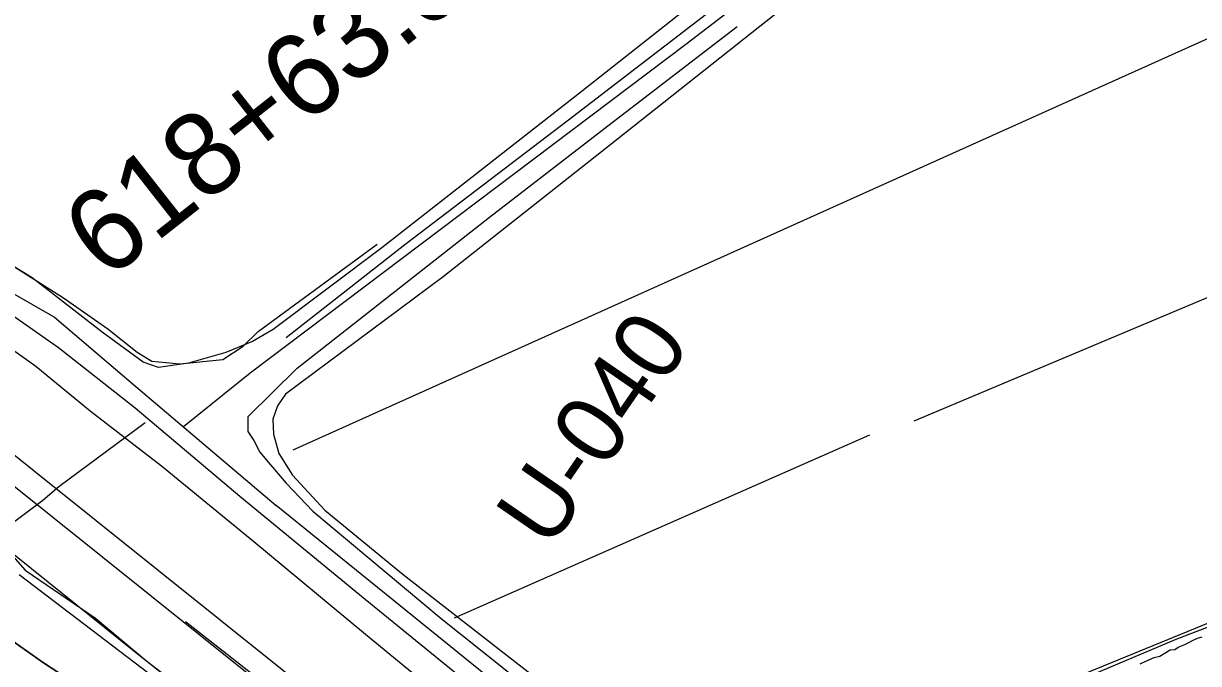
# Model space of a CAD drawing. Extents: x 3329297 to 3367176, y 649250 to 674653.
# Drawn here: x 3339953 to 3341368, y 669863 to 670634 of the extents above; entities that cross this region are included whole.
import ezdxf

# ---------------------------------------------------------------- set-up
doc = ezdxf.new("R2010")
doc.units = 0
for name, color, linetype in [('V-BORW-LINE', 7, 'Continuous'), ('V-DTCH-CNTR', 7, 'Continuous'), ('V-FLOD-BASE', 7, 'Continuous'), ('V-LEVE-TOET', 7, 'Continuous'), ('V-RIVR-RANG-IDEN', 7, 'Continuous'), ('V-ROAD-CNTR', 7, 'Continuous'), ('V-SITE-VEGE', 7, 'Continuous'), ('V-SURV-IDEN', 7, 'Continuous'), ('V-SURV-LINE', 7, 'Continuous'), ('V-TOPO-SHOR', 7, 'Continuous'), ('V-UTIL-LINE', 7, 'Continuous'), ('V-WETL-SWMP', 7, 'Continuous')]:
    doc.layers.add(name, color=color, linetype=linetype)

msp = doc.modelspace()

# ---------------------------------------------------------------- linework, layer by layer
at = {"layer": 'V-BORW-LINE'}
for points in [[(3338746.2, 670499.1), (3338751.5, 670497.1), (3339072.9, 670329.3), (3339297.5, 670198.9), (3339509.9, 670071.7), (3339743.3, 669952.6), (3339874.8, 669804.3), (3340076.4, 669714), (3340201.3, 669657), (3340187.6, 669710.9), (3340092.4, 669788.9), (3339977.3, 669864.2), (3339881.3, 669931.4), (3339745.1, 670037.3), (3339620.9, 670105.1), (3339504.8, 670191.3), (3339378.1, 670257.4), (3339267.1, 670330.2)], [(3339881.3, 669931.4), (3339977.3, 669864.2), (3340092.4, 669788.9), (3340187.6, 669710.9), (3340201.3, 669657), (3340076.4, 669714), (3339874.8, 669804.3)]]:
    msp.add_lwpolyline(points, dxfattribs=at)
at = {"layer": 'V-DTCH-CNTR'}
msp.add_lwpolyline([(3340905.5, 670682.6), (3340649.3, 670479.5), (3340458.8, 670328.7), (3340268.8, 670187.4), (3340259.1, 670173.6), (3340253.4, 670157.6), (3340254.1, 670139.5), (3340260.5, 670116.1), (3340277.3, 670090), (3340316, 670048.1), (3340410.4, 669970.6), (3340581.1, 669837.6), (3340758.7, 669686.8), (3340779, 669671.8), (3340784.6, 669669.7), (3340796.4, 669670.2), (3340890.2, 669711.6), (3341407, 669923.1)], dxfattribs=at)
at = {"layer": 'V-FLOD-BASE'}
msp.add_lwpolyline([(3340148.2, 669914), (3340365.8, 669743.1), (3340588.7, 669560.5), (3340765.6, 669415.8)], dxfattribs=at)
at = {"layer": 'V-LEVE-TOET'}
for points in [[(3339894.4, 670273.3), (3339967.8, 670221.4), (3340033.4, 670167.6), (3340119.2, 670101.1), (3340230.7, 670010.2), (3340365.1, 669898.7), (3340497.8, 669789.6), (3340649.9, 669672.5), (3340747.9, 669599.3), (3340757.4, 669596.8)], [(3340780.9, 669341.3), (3340768.5, 669352.2), (3340706.9, 669385.5), (3340663.6, 669419.5), (3340583.5, 669479.9), (3340455.8, 669582.1), (3340360.3, 669658), (3340172.8, 669809.5), (3340086.1, 669878.3), (3339928, 670005.5)]]:
    msp.add_lwpolyline(points, dxfattribs=at)
at = {"layer": 'V-ROAD-CNTR'}
for points in [[(3343701, 672838.7), (3343536.9, 672714.2), (3343326.8, 672557.6), (3343073.9, 672369.6), (3342849.9, 672197.9), (3342589.8, 672003.1), (3342295.7, 671781.2), (3341863.4, 671455.5), (3341721, 671349), (3341633.9, 671281), (3341381.4, 671091.4), (3340750.8, 670608.5), (3340226.3, 670212.7), (3340145.7, 670148.2)], [(3339935.7, 670311.7), (3339990.3, 670280.1), (3340088.3, 670197), (3340257.3, 670053.5)], [(3341367.6, 669149.5), (3340835.9, 669585.6), (3340257.3, 670053.5)]]:
    msp.add_lwpolyline(points, dxfattribs=at)
at = {"layer": 'V-SITE-VEGE'}
for p, q in [((3340882.7, 670755.3), (3340626.4, 670552.9)), ((3340626.4, 670552.9), (3340384.6, 670363.7)), ((3339963.5, 670327.5), (3339879.5, 670379.2)), ((3340384.6, 670363.7), (3340253.9, 670265.6)), ((3340048, 670262.4), (3339963.5, 670327.5)), ((3340253.9, 670265.6), (3340229, 670251.1)), ((3340097.1, 670226.1), (3340048, 670262.4)), ((3340229, 670251.1), (3340196.9, 670237.9)), ((3340196.9, 670237.9), (3340152, 670225)), ((3340115.6, 670219.6), (3340097.1, 670226.1)), ((3340152, 670225), (3340115.6, 670219.6))]:
    msp.add_line(p, q, dxfattribs=at)
msp.add_lwpolyline([(3341298.2, 669862.9), (3341305.1, 669866), (3341314.8, 669870.6), (3341321.7, 669872.2), (3341327.2, 669875.3), (3341334.1, 669879.7), (3341339.7, 669880), (3341343.8, 669882.9), (3341352.1, 669886.1), (3341357.7, 669889.1), (3341360.4, 669890.6), (3341367.3, 669893.7), (3341372.9, 669895.3)], dxfattribs=at)
at = {"layer": 'V-SURV-LINE'}
for points in [[(3339891.1, 670155.1), (3341235.6, 669078.5)], [(3341216.9, 669055), (3339872.3, 670131.6)]]:
    msp.add_lwpolyline(points, dxfattribs=at)
at = {"layer": 'V-TOPO-SHOR'}
for p, q in [((3340278, 670120.4), (3341747.2, 670781)), ((3341025.8, 670155.5), (3341865.8, 670508.5)), ((3340472.3, 669918.3), (3340972.4, 670138.5))]:
    msp.add_line(p, q, dxfattribs=at)
for points in [[(3336581, 671929.3), (3336911.3, 671788), (3337497.3, 671540.7), (3337719.2, 671445.3), (3338024.6, 671316.4), (3338243.1, 671222.8), (3338449, 671136.2), (3338537.8, 671092), (3338731.4, 670993), (3339100.8, 670796.8), (3339280.2, 670699.6), (3339711.8, 670471.5), (3339889.4, 670374.2), (3340001.3, 670303.5), (3340054.6, 670266.3), (3340090.1, 670238), (3340107.9, 670227.4), (3340141.6, 670223.9), (3340193.1, 670229.3), (3340217.9, 670245.3), (3340235.6, 670263.1), (3340379.1, 670368.1)], [(3340269.4, 670255.8), (3340412.3, 670367.9), (3340609.4, 670518), (3340874.5, 670721.6), (3341158.1, 670937.8), (3341293.5, 671037.8)], [(3340282.8, 670218.9), (3340514.5, 670400.5), (3340662.1, 670514.5), (3340812.8, 670630.1)], [(3340745.1, 669630.7), (3340364.8, 669940.5), (3340213.8, 670064.4), (3340087.6, 670170.6), (3339995.2, 670243.2), (3339917, 670298), (3339792.7, 670361.6), (3339606.2, 670467.7), (3339464.1, 670540.2)], [(3340282.8, 670218.9), (3340223.4, 670160.2), (3340223.4, 670142.5), (3340230.5, 670131.8), (3340237.6, 670117.6), (3340248.3, 670105.2), (3340269.6, 670080.4), (3340301.6, 670046.8), (3340456.2, 669917.6), (3340529.1, 669859.1), (3340781.4, 669655.6), (3341341.6, 669892.6), (3341946.2, 670124.4), (3342009.2, 670152.9), (3341950.3, 670298.3)]]:
    msp.add_lwpolyline(points, dxfattribs=at)
at = {"layer": 'V-UTIL-LINE'}
msp.add_lwpolyline([(3339897.2, 670000.8), (3339976.6, 670060.1), (3339995.7, 670076.4), (3340099.7, 670153.6)], dxfattribs=at)
at = {"layer": 'V-WETL-SWMP'}
for p, q in [((3339931.6, 670002.6), (3339955.1, 669975.5)), ((3340228.1, 669756.9), (3339947.8, 669970.2)), ((3339955.1, 669975.5), (3340040, 669917.7)), ((3340040, 669917.7), (3340101.5, 669866.1)), ((3340101.5, 669866.1), (3340225.4, 669772.1))]:
    msp.add_line(p, q, dxfattribs=at)

# ---------------------------------------------------------------- texts
at = {"layer": 'V-RIVR-RANG-IDEN'}
msp.add_text('U-040', height=83, rotation=55.4859, dxfattribs=at).set_placement((3340586.6, 669998.9))
at = {"layer": 'V-SURV-IDEN'}
msp.add_text('618+63.9', height=100, rotation=38.162, dxfattribs=at).set_placement((3340053.3, 670323.1))

doc.saveas('drawing.dxf')
